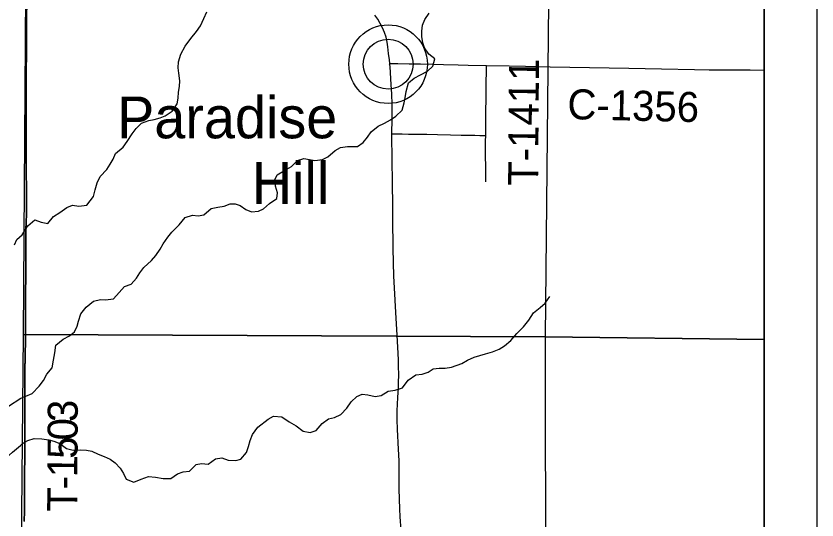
# Model space of a CAD drawing. Extents: x 0 to 34, y 0 to 22.
# Drawn here: x 7.484 to 9, y 14.926 to 15.879 of the extents above; entities that cross this region are included whole.
import ezdxf

# ---------------------------------------------------------------- set-up
doc = ezdxf.new("R2010")
doc.units = 0
for name, color, linetype in [('Default', 7, 'Continuous'), ('GM_X_County_Road', 7, 'Continuous'), ('GM_X_County_Road_Text', 7, 'Continuous'), ('GM_X_Minor_River', 7, 'Continuous'), ('GM_X_Section', 7, 'Continuous'), ('GM_X_State_Route', 7, 'Continuous'), ('GM_X_Township_Road', 7, 'Continuous'), ('GM_X_Township_Road_Text', 7, 'Continuous'), ('GM_X_Unincorporated', 7, 'Continuous'), ('GM_X_Unincorporated_Location', 7, 'Continuous'), ('GM_X_Unincorporated_Text', 7, 'Continuous'), ('SH_Cut_Line', 7, 'Continuous'), ('SH_Data', 7, 'Continuous')]:
    doc.layers.add(name, color=color, linetype=linetype)

msp = doc.modelspace()

# ---------------------------------------------------------------- linework, layer by layer
at = {"layer": 'Default'}
for points in [[(8.9, 14.1), (8.9, 18.2728)], [(7.5041, 15.9172), (7.5038, 15.8644), (7.5038, 15.8489), (7.5035, 15.824), (7.5033, 15.8086), (7.5031, 15.7745), (7.5027, 15.7281), (7.5026, 15.7064), (7.5028, 15.6722), (7.5031, 15.6163), (7.503, 15.5977), (7.5032, 15.5387), (7.5033, 15.5265), (7.5033, 15.5045), (7.503, 15.4893), (7.5025, 15.4745), (7.5024, 15.4612), (7.5024, 15.4458), (7.5022, 15.427), (7.5023, 15.4053), (7.5021, 15.3804), (7.5018, 15.362), (7.5015, 15.3154), (7.5014, 15.2939), (7.5013, 15.2657), (7.5011, 15.2376), (7.5006, 15.2065), (7.5005, 15.1879), (7.5005, 15.1818), (7.5006, 15.1755), (7.5006, 15.1556), (7.5006, 15.1484), (7.5006, 15.1391), (7.5006, 15.1351), (7.5006, 15.1308), (7.5006, 15.1277), (7.5006, 15.1247), (7.5005, 15.1219), (7.5002, 15.113), (7.5001, 15.1008), (7.5003, 15.0757), (7.5002, 15.0478), (7.4999, 15.0104), (7.4998, 14.9887), (7.4995, 14.9638), (7.4994, 14.9421), (7.4992, 14.9234)], [(7.4992, 14.9234), (7.4994, 14.9421), (7.4995, 14.9638), (7.4998, 14.9887), (7.4999, 15.0104), (7.5002, 15.0478), (7.5003, 15.0757), (7.5001, 15.1008), (7.5002, 15.113), (7.5005, 15.1219), (7.5006, 15.1247), (7.5006, 15.1277), (7.5006, 15.1308), (7.5006, 15.1351), (7.5006, 15.1391), (7.5006, 15.1484), (7.5006, 15.1556), (7.5006, 15.1755), (7.5005, 15.1818), (7.5005, 15.1879), (7.5006, 15.2065), (7.5011, 15.2376), (7.5013, 15.2657), (7.5014, 15.2939), (7.5015, 15.3154), (7.5018, 15.362), (7.5021, 15.3804), (7.5023, 15.4053), (7.5022, 15.427), (7.5024, 15.4458), (7.5024, 15.4612), (7.5025, 15.4745), (7.503, 15.4893), (7.5033, 15.5045), (7.5033, 15.5265), (7.5032, 15.5387), (7.503, 15.5977), (7.5031, 15.6163), (7.5028, 15.6722), (7.5026, 15.7064), (7.5027, 15.7281), (7.5031, 15.7745), (7.5033, 15.8086), (7.5035, 15.824), (7.5038, 15.8489), (7.5038, 15.8644), (7.5041, 15.9172)]]:
    msp.add_lwpolyline(points, dxfattribs=at)
for points in [[(8.9, 15.267), (8.9, 16.282), (8.4953, 16.2856), (8.4854, 15.2725)], [(8.9, 14.2515), (8.9, 15.267), (8.4854, 15.2725), (8.4865, 14.2546)]]:
    msp.add_lwpolyline(points, close=True, dxfattribs=at)
at = {"layer": 'GM_X_County_Road'}
for points in [[(8.1911, 15.7895), (8.2067, 15.7893), (8.2278, 15.789), (8.2497, 15.7886), (8.273, 15.7881), (8.2931, 15.7877), (8.3209, 15.787), (8.3396, 15.7867), (8.3743, 15.786)], [(8.3743, 15.786), (8.4173, 15.785), (8.4483, 15.7843), (8.4949, 15.7835), (8.5321, 15.7825), (8.6439, 15.7804), (8.7059, 15.7793), (8.768, 15.778), (8.7961, 15.7777), (8.8737, 15.7774), (8.9, 15.7771)]]:
    msp.add_lwpolyline(points, dxfattribs=at)
at = {"layer": 'GM_X_Minor_River'}
for points in [[(7.4927, 15.1562), (7.5023, 15.1598), (7.514, 15.165), (7.5273, 15.179), (7.5354, 15.1895), (7.5423, 15.2014), (7.5522, 15.2138), (7.5549, 15.2282), (7.5569, 15.2423), (7.5592, 15.2568), (7.5726, 15.2681), (7.5849, 15.2745), (7.5946, 15.2819), (7.5993, 15.2923), (7.6017, 15.3022), (7.6063, 15.3156), (7.6163, 15.3287), (7.6304, 15.3397), (7.6436, 15.3431), (7.6531, 15.3421), (7.6682, 15.344), (7.6789, 15.356), (7.6893, 15.3673), (7.7017, 15.3718), (7.7116, 15.383), (7.7182, 15.3934), (7.7255, 15.4038), (7.74, 15.4167), (7.7481, 15.4264), (7.7566, 15.4383), (7.762, 15.4483), (7.7708, 15.4607), (7.7789, 15.4704), (7.7926, 15.484), (7.8037, 15.4983), (7.8176, 15.5024), (7.8282, 15.5011), (7.8392, 15.5033), (7.8529, 15.5154), (7.8657, 15.5176), (7.8778, 15.5194), (7.8891, 15.5238), (7.8986, 15.5237), (7.9081, 15.5209), (7.9189, 15.5135), (7.9296, 15.5089), (7.9425, 15.5103), (7.9522, 15.5147), (7.9637, 15.5248), (7.9771, 15.5339), (7.9784, 15.5445), (7.9751, 15.5577), (7.9737, 15.5695), (7.978, 15.5791), (7.9918, 15.587), (8.0049, 15.5949), (8.0168, 15.6058), (8.0288, 15.6099), (8.0395, 15.6079), (8.0494, 15.6062), (8.0641, 15.6081), (8.0742, 15.6128), (8.0879, 15.6249), (8.098, 15.6305), (8.1109, 15.6323), (8.1204, 15.6322), (8.1302, 15.6324), (8.1406, 15.6399), (8.1491, 15.6499), (8.1561, 15.66), (8.1691, 15.6709), (8.1811, 15.6765), (8.1927, 15.6828), (8.2024, 15.6899), (8.215, 15.7012), (8.2185, 15.7153), (8.2201, 15.7248), (8.2221, 15.7367), (8.2267, 15.7527), (8.2375, 15.7617), (8.2491, 15.7684), (8.2625, 15.7752), (8.2726, 15.7842), (8.2768, 15.7983), (8.2652, 15.8075), (8.257, 15.8191), (8.2537, 15.8289), (8.2519, 15.8406), (8.2517, 15.8508), (8.2533, 15.8619), (8.2573, 15.8726), (8.2661, 15.8849)], [(7.4952, 15.4654), (7.5062, 15.4821), (7.5192, 15.4934), (7.5311, 15.4891), (7.544, 15.4868), (7.5547, 15.4999), (7.5663, 15.5078), (7.5801, 15.5169), (7.5906, 15.5217), (7.6027, 15.5197), (7.6175, 15.5215), (7.6304, 15.5378), (7.6335, 15.5504), (7.637, 15.5638), (7.6431, 15.576), (7.6553, 15.5892), (7.6619, 15.5989), (7.6674, 15.6085), (7.672, 15.6192), (7.6865, 15.6313), (7.6939, 15.6418), (7.7038, 15.6564), (7.7111, 15.6665), (7.7211, 15.6766), (7.7354, 15.6818), (7.7452, 15.6836), (7.7565, 15.6865), (7.7662, 15.6905), (7.7793, 15.6992), (7.7885, 15.7131), (7.7909, 15.7238), (7.7914, 15.7352), (7.793, 15.7462), (7.7935, 15.7568), (7.7917, 15.7712), (7.7907, 15.7814), (7.7912, 15.7925), (7.7957, 15.8074), (7.8037, 15.8223), (7.8148, 15.837), (7.8254, 15.8498), (7.8328, 15.8606), (7.8393, 15.8744), (7.8447, 15.8875)], [(7.4805, 15.4464), (7.485, 15.4563), (7.4952, 15.4654)], [(7.492, 15.0664), (7.4957, 15.0705), (7.5062, 15.0761), (7.5178, 15.0797), (7.5323, 15.0793), (7.5456, 15.0774), (7.5551, 15.0749), (7.5666, 15.0707), (7.5793, 15.0611), (7.5919, 15.0576), (7.6059, 15.0583), (7.6172, 15.0578), (7.6271, 15.0558), (7.6394, 15.0504), (7.6505, 15.0457), (7.6616, 15.041), (7.6716, 15.0337), (7.6806, 15.024), (7.6869, 15.0136), (7.6924, 15.0031), (7.7066, 14.9973), (7.7204, 15.003), (7.7344, 15.0079), (7.748, 15.007), (7.7625, 15.004), (7.7765, 15.0043), (7.7895, 15.0133), (7.8001, 15.0166), (7.8122, 15.0184), (7.8248, 15.0305), (7.835, 15.0323), (7.8471, 15.0314), (7.8616, 15.0416), (7.873, 15.0434), (7.8852, 15.0391), (7.8996, 15.0383), (7.9094, 15.0409), (7.9201, 15.0536), (7.9236, 15.0647), (7.9271, 15.0762), (7.9311, 15.0873), (7.9413, 15.1016), (7.9607, 15.1165), (7.9712, 15.1224), (7.9867, 15.1209), (8.001, 15.1117), (8.0137, 15.104), (8.0271, 15.0941), (8.0405, 15.091), (8.0517, 15.0951), (8.0632, 15.1083), (8.0755, 15.1169), (8.0868, 15.1198), (8.0988, 15.1254), (8.1099, 15.1371), (8.1183, 15.1494), (8.1287, 15.1591), (8.1392, 15.1636), (8.1495, 15.1627), (8.1636, 15.1592), (8.1749, 15.161), (8.1879, 15.1693), (8.2015, 15.1711), (8.2155, 15.176), (8.2261, 15.1903), (8.2403, 15.2005), (8.2527, 15.2016), (8.2636, 15.2056), (8.2734, 15.2115), (8.2847, 15.2133), (8.2964, 15.2132), (8.3081, 15.215), (8.3277, 15.2216), (8.3385, 15.2279), (8.3513, 15.2339), (8.3618, 15.2372), (8.3723, 15.2401), (8.3855, 15.2442), (8.3983, 15.249), (8.4084, 15.255), (8.4203, 15.2655), (8.4317, 15.2783), (8.4447, 15.2911), (8.4546, 15.3039), (8.4634, 15.3178), (8.4757, 15.3275), (8.4857, 15.3357), (8.4945, 15.3485)], [(7.4693, 15.1411), (7.4927, 15.1562)], [(7.3813, 15.0001), (7.3896, 14.9992), (7.4006, 15.0026), (7.4113, 15.0076), (7.4215, 15.0121), (7.4321, 15.0174), (7.445, 15.0269), (7.4545, 15.0353), (7.4651, 15.0436), (7.4772, 15.0538), (7.492, 15.0664)]]:
    msp.add_lwpolyline(points, dxfattribs=at)
at = {"layer": 'GM_X_Section'}
for points in [[(7.5047, 16.2943), (8.4953, 16.2856), (8.4854, 15.2725), (7.4976, 15.2767)], [(7.4976, 15.2767), (8.4854, 15.2725), (8.4865, 14.2546), (7.4886, 14.263)]]:
    msp.add_lwpolyline(points, close=True, dxfattribs=at)
at = {"layer": 'GM_X_State_Route'}
msp.add_lwpolyline([(8.2125, 14.9066), (8.2111, 14.9314), (8.2103, 14.9469), (8.2093, 14.9841), (8.209, 14.9965), (8.2089, 15.0027), (8.2091, 15.012), (8.2092, 15.0151), (8.2092, 15.0182), (8.2091, 15.0306), (8.2088, 15.0368), (8.2083, 15.0492), (8.207, 15.0708), (8.2062, 15.0863), (8.2058, 15.0956), (8.2057, 15.0987), (8.2051, 15.1142), (8.2052, 15.1232), (8.2053, 15.1325), (8.2066, 15.1572), (8.2075, 15.1759), (8.2079, 15.1883), (8.2081, 15.1976), (8.2077, 15.2193), (8.2075, 15.2286), (8.207, 15.241), (8.2051, 15.2752), (8.2028, 15.3186), (8.2001, 15.3651), (8.1991, 15.3868), (8.1977, 15.4396), (8.1971, 15.4955), (8.1969, 15.5141), (8.1961, 15.57), (8.1959, 15.6016), (8.1956, 15.6196), (8.1954, 15.6411), (8.1951, 15.6565), (8.1957, 15.6848), (8.1958, 15.6973), (8.1957, 15.7128), (8.195, 15.7314), (8.1941, 15.75), (8.1927, 15.7717), (8.1917, 15.7839), (8.1914, 15.787), (8.1911, 15.7895), (8.1904, 15.7962), (8.1891, 15.8086), (8.1877, 15.821), (8.1862, 15.8302), (8.1841, 15.8394), (8.1812, 15.8483), (8.1775, 15.857), (8.1733, 15.8653), (8.1684, 15.8734), (8.163, 15.881)], dxfattribs=at)
at = {"layer": 'GM_X_Township_Road'}
for points in [[(7.4994, 14.9229), (7.4996, 14.9415), (7.4998, 14.9633), (7.5, 14.9881), (7.5001, 15.0099), (7.5004, 15.0472), (7.5005, 15.0752), (7.5003, 15.1002), (7.5005, 15.1125), (7.5007, 15.1213), (7.5008, 15.1242), (7.5008, 15.1271), (7.5008, 15.1303), (7.5008, 15.1345), (7.5008, 15.1386), (7.5008, 15.1478), (7.5008, 15.155), (7.5008, 15.175), (7.5007, 15.1812), (7.5007, 15.1874), (7.5009, 15.206), (7.5013, 15.2371), (7.5015, 15.2651), (7.5016, 15.2933), (7.5018, 15.3148), (7.502, 15.3614), (7.5024, 15.3799), (7.5025, 15.4047), (7.5024, 15.4265), (7.5026, 15.4453), (7.5026, 15.4607), (7.5027, 15.4739), (7.5032, 15.4888), (7.5035, 15.5039), (7.5035, 15.5259), (7.5034, 15.5381), (7.5032, 15.5972), (7.5033, 15.6158), (7.503, 15.6717), (7.5028, 15.7058), (7.5029, 15.7276), (7.5033, 15.774), (7.5035, 15.808), (7.5037, 15.8235), (7.504, 15.8483), (7.504, 15.8638), (7.5043, 15.9167)], [(8.3728, 15.6534), (8.373, 15.6602), (8.3731, 15.6691), (8.3733, 15.6967), (8.3736, 15.7249), (8.3737, 15.7436), (8.3738, 15.7561), (8.3741, 15.7718), (8.3743, 15.7834), (8.3743, 15.786)], [(8.1951, 15.6565), (8.1983, 15.6564), (8.2056, 15.6563), (8.2149, 15.6563), (8.2269, 15.6558), (8.2456, 15.6556), (8.2611, 15.6555), (8.2817, 15.655), (8.3064, 15.6546), (8.3264, 15.6542), (8.3523, 15.6539), (8.362, 15.6536), (8.3728, 15.6534)], [(8.3732, 15.5653), (8.3729, 15.5936), (8.3725, 15.6154), (8.3724, 15.6279), (8.3726, 15.6428), (8.3728, 15.6534)]]:
    msp.add_lwpolyline(points, dxfattribs=at)
at = {"layer": 'GM_X_Unincorporated'}
for radius in [0.0744, 0.0472]:
    msp.add_circle((8.1881, 15.7883), radius, dxfattribs=at)
at = {"layer": 'GM_X_Unincorporated_Location'}
msp.add_line((8.1881, 15.7883), (8.1881, 15.7883), dxfattribs=at)
at = {"layer": 'SH_Cut_Line'}
for points in [[(8.9, 14.1), (8.9, 20.9)], [(7.4992, 14.9234), (7.4994, 14.9421), (7.4995, 14.9638), (7.4998, 14.9887), (7.4999, 15.0104), (7.5002, 15.0478), (7.5003, 15.0757), (7.5001, 15.1008), (7.5002, 15.113), (7.5005, 15.1219), (7.5006, 15.1247), (7.5006, 15.1277), (7.5006, 15.1308), (7.5006, 15.1351), (7.5006, 15.1391), (7.5006, 15.1484), (7.5006, 15.1556), (7.5006, 15.1755), (7.5005, 15.1818), (7.5005, 15.1879), (7.5006, 15.2065), (7.5011, 15.2376), (7.5013, 15.2657), (7.5014, 15.2939), (7.5015, 15.3154), (7.5018, 15.362), (7.5021, 15.3804), (7.5023, 15.4053), (7.5022, 15.427), (7.5024, 15.4458), (7.5024, 15.4612), (7.5025, 15.4745), (7.503, 15.4893), (7.5033, 15.5045), (7.5033, 15.5265), (7.5032, 15.5387), (7.503, 15.5977), (7.5031, 15.6163), (7.5028, 15.6722), (7.5026, 15.7064), (7.5027, 15.7281), (7.5031, 15.7745), (7.5033, 15.8086), (7.5035, 15.824), (7.5038, 15.8489), (7.5038, 15.8644), (7.5041, 15.9172)], [(7.5041, 15.9172), (7.5038, 15.8644), (7.5038, 15.8489), (7.5035, 15.824), (7.5033, 15.8086), (7.5031, 15.7745), (7.5027, 15.7281), (7.5026, 15.7064), (7.5028, 15.6722), (7.5031, 15.6163), (7.503, 15.5977), (7.5032, 15.5387), (7.5033, 15.5265), (7.5033, 15.5045), (7.503, 15.4893), (7.5025, 15.4745), (7.5024, 15.4612), (7.5024, 15.4458), (7.5022, 15.427), (7.5023, 15.4053), (7.5021, 15.3804), (7.5018, 15.362), (7.5015, 15.3154), (7.5014, 15.2939), (7.5013, 15.2657), (7.5011, 15.2376), (7.5006, 15.2065), (7.5005, 15.1879), (7.5005, 15.1818), (7.5006, 15.1755), (7.5006, 15.1556), (7.5006, 15.1484), (7.5006, 15.1391), (7.5006, 15.1351), (7.5006, 15.1308), (7.5006, 15.1277), (7.5006, 15.1247), (7.5005, 15.1219), (7.5002, 15.113), (7.5001, 15.1008), (7.5003, 15.0757), (7.5002, 15.0478), (7.4999, 15.0104), (7.4998, 14.9887), (7.4995, 14.9638), (7.4994, 14.9421), (7.4992, 14.9234)]]:
    msp.add_lwpolyline(points, dxfattribs=at)
at = {"layer": 'SH_Data'}
for p, q in [((9, 21), (9, 14)), ((8.9, 20.9), (8.9, 14.1))]:
    msp.add_line(p, q, dxfattribs=at)

# ---------------------------------------------------------------- texts
at = {"layer": 'GM_X_County_Road_Text'}
msp.add_text('C-1356', height=0.05682, rotation=358.6361, dxfattribs=at).set_placement((8.527, 15.6844))
at = {"layer": 'GM_X_Township_Road_Text'}
for s, height, rotation, p in [('T-1411', 0.05682, 89.558, (8.472, 15.5579)), ('3', 0.0568, 89.6409, (7.6004, 15.1108)), ('0', 0.0568, 89.6381, (7.6002, 15.0761)), ('5', 0.0568, 89.6356, (7.6, 15.0413)), ('1', 0.0568, 89.6346, (7.5997, 15.0066)), ('-', 0.0568, 89.6268, (7.5996, 14.9835)), ('T', 0.0568, 89.5889, (7.5993, 14.941))]:
    msp.add_text(s, height=height, rotation=rotation, dxfattribs=at).set_placement(p)
at = {"layer": 'GM_X_Unincorporated_Text'}
for s, p in [('Paradise', (7.675, 15.648)), ('Hill', (7.93, 15.5239))]:
    msp.add_text(s, height=0.07898, rotation=0, dxfattribs=at).set_placement(p)

doc.saveas('drawing.dxf')
